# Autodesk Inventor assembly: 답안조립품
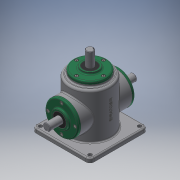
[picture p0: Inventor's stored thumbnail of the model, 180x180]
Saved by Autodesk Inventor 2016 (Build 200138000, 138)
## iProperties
Created: 2019-08
Part Number: 답안조립품
Material: 일반
Document SubType Name: Assembly
Designer: user
Author: user
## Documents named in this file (16)
- D:\490823V1007\답안조립품.iam
- D:\490823V1007\본체.ipt
- D:\490823V1007\메인 베벨기어.ipt
- D:\490823V1007\메인 축.ipt
- 메인 축.ipt
- D:\490823V1007\베어링 6203.ipt
- D:\490823V1007\볼트 M4.ipt
- 볼트 M4.ipt
- D:\490823V1007\서브 베벨기어.ipt
- D:\490823V1007\서브 축.ipt
- 서브 축.ipt
- D:\490823V1007\오일 실.ipt
- 오일 실.ipt
- D:\490823V1007\커버.ipt
- D:\490823V1007\키 4x4.ipt
- D:\490823V1007\키 5x5.ipt
